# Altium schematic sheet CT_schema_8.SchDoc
size 147 x 119 mm
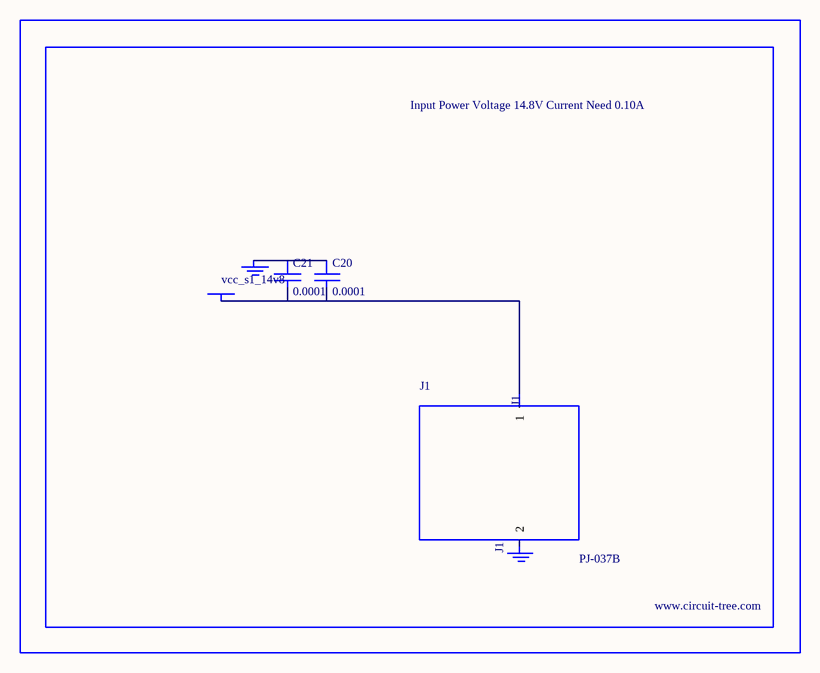
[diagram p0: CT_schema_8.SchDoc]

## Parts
BORDER7  (no value)
C20  0.0001  [EXV-9H]
C21  0.0001  [EXV-9H]
GND_INSTANCE_7_0  (no value)
GND_INSTANCE_7_1  (no value)
J1  PJ-037B  [PJ-037B_PACKAGE]
POWER_INSTANCE_7_0  vcc_s1_14v8

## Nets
NetC20_1: C20.1 C21.1 GND_INSTANCE_7_0.0(GND)
NetC20_2: C20.2 C21.2 J1.1 POWER_INSTANCE_7_0.0(PWR)

Not connected (* = marked no-connect by the designer): GND_INSTANCE_7_1 0(GND); J1 2

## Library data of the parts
BORDER7 = BORDER_PAGE7
C20 C21 = EDK107M035A9HAA
GND_INSTANCE_7_0 GND_INSTANCE_7_1 = GND
POWER_INSTANCE_7_0 = PWR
